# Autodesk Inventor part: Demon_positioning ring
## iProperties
Shininess: 64.0
Length Units: 11269
Angle Units: 11279
Time Units: 11290
Mass Units: 11283
Length Display Precision: 3
Angle Display Precision: 2
Compacted: True
Part Number: Demon_positioning ring
Document SubType Name: Modeling
Created: 2005-04
Material: Aluminum-6061
Designer: John Blackburn
Manufacturer: Standard
Standards Organization: Custom
Density: 0.0
Volumn: 0.0
Area: 0.0
PropertySet Name: Model Information
Control State: 0
Master: False
Checked Out: False
Author: John Blackburn
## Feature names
1. Extrusion1
2. Hole1
3. Chamfer1
4. Hole2
5. Circular Pattern1
